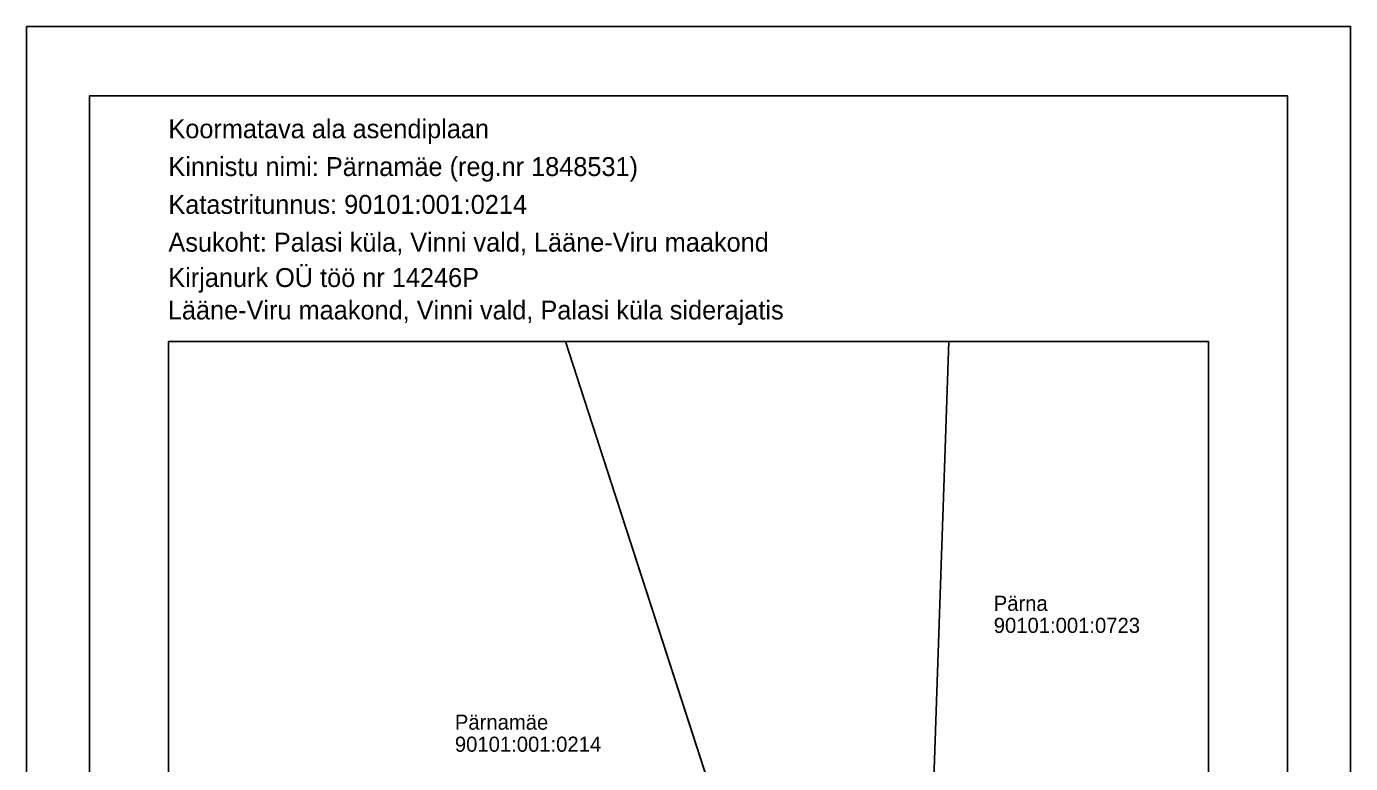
# Model space of a CAD drawing. Extents: x 656051.4 to 656103.9, y 6569049.3 to 6569123.6.
# Drawn here: x 656051.4 to 656103.9, y 6569094.4 to 6569123.6 of the extents above; entities that cross this region are included whole.
import ezdxf

# ---------------------------------------------------------------- set-up
doc = ezdxf.new("R2010")
doc.units = 0
for name, color, linetype in [('MPOHULIIN', 7, 'Continuous'), ('OL_SIDE', 7, 'Continuous'), ('PIIR', 7, 'Continuous'), ('VORMISTUS', 7, 'Continuous')]:
    doc.layers.add(name, color=color, linetype=linetype)

msp = doc.modelspace()

# ---------------------------------------------------------------- linework, layer by layer
at = {"layer": 'MPOHULIIN'}
msp.add_lwpolyline([(656098.302, 6569093.579), (656080.732, 6569086.608), (656072.8, 6569111.089)], dxfattribs=at)
at = {"layer": 'OL_SIDE'}
msp.add_line((656080.732, 6569086.608), (656072.8, 6569111.089), dxfattribs=at)
at = {"layer": 'PIIR'}
for points in [[(656057.052, 6569074.137), (656087.16, 6569086.39), (656087.997, 6569111.089)], [(656087.997, 6569111.089), (656087.16, 6569086.39), (656098.302, 6569093.341)]]:
    msp.add_lwpolyline(points, dxfattribs=at)
at = {"layer": 'VORMISTUS'}
for points in [[(656051.427, 6569123.589), (656103.927, 6569123.589), (656103.927, 6569049.339), (656051.427, 6569049.339)], [(656053.927, 6569052.089), (656101.427, 6569052.089), (656101.427, 6569120.839), (656053.927, 6569120.839)], [(656053.927, 6569120.839), (656101.427, 6569120.839), (656101.427, 6569052.089), (656053.927, 6569052.089)], [(656098.302, 6569058.589), (656057.052, 6569058.589), (656057.052, 6569111.089), (656098.302, 6569111.089)]]:
    msp.add_lwpolyline(points, close=True, dxfattribs=at)

# ---------------------------------------------------------------- texts
at = {"layer": 'PIIR'}
for s, p in [('Pärna', (656089.78, 6569100.407)), ('90101:001:0723', (656089.78, 6569099.532)), ('Pärnamäe', (656068.414, 6569095.692)), ('90101:001:0214', (656068.414, 6569094.817))]:
    msp.add_text(s, height=0.6, dxfattribs=at).set_placement(p)
at = {"layer": 'VORMISTUS'}
for s, p in [('Koormatava ala asendiplaan', (656057.055, 6569119.156)), ('Kinnistu nimi: Pärnamäe (reg.nr 1848531)', (656057.055, 6569117.656)), ('Katastritunnus: 90101:001:0214', (656057.055, 6569116.156)), ('Asukoht: Palasi küla, Vinni vald, Lääne-Viru maakond', (656057.055, 6569114.656))]:
    msp.add_text(s, height=0.75, dxfattribs=at).set_placement(p)
for s, p in [('Kirjanurk OÜ töö nr 14246P', (656057.051, 6569113.254)), ('Lääne-Viru maakond, Vinni vald, Palasi küla siderajatis', (656057.032, 6569111.967))]:
    msp.add_text(s, height=0.75, rotation=360, dxfattribs=at).set_placement(p)

doc.saveas('drawing.dxf')
